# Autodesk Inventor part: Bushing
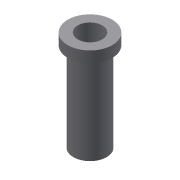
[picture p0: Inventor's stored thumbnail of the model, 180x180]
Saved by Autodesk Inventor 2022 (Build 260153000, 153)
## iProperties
Created: 2002-02
Part Number: Bushing
Document SubType Name: Modeling
Designer: ***
Density: 1 g/cm^3
Material: Generic
Appearance: Default
Control State: 0
Master: False
Checked Out: False
Shininess: 77.0
Length Units: 11269
Angle Units: 11279
Time Units: 11290
Mass Units: 11283
Length Display Precision: 3
Angle Display Precision: 2
Density: 0.0
Volumn: 0.0
Area: 0.0
PropertySet Name: Model Information
Author: ***
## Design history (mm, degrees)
sketch "Sketch2"
  geometry: C1 r 10 at (0, 0); 1 further point
  constraints: 1 centre point, 1 coincident
  dimensions: "d8" = 20 diameter of C1
extrude "Extrusion1" new body sketch "Sketch2" distance "d6" = 5; taper "d7" = 0 deg
sketch "Sketch4"
  geometry: C1 r 7.5 at (0, 0); 1 further point
  constraints: 1 centre point, 1 coincident
  dimensions: "d9" = 15 diameter of C1
extrude "Extrusion2" join sketch "Sketch4" distance "d10" = 40; taper "d11" = 0 deg
sketch "Sketch5"
  geometry: C1 r 5.5 at (0, 0); 1 further point
  constraints: 1 centre point, 1 coincident
  dimensions: "d12" = 11 diameter of C1
extrude "Extrusion3" cut sketch "Sketch5" distance "d13" = 57.75; taper "d14" = 0 deg
body "Solid2"
